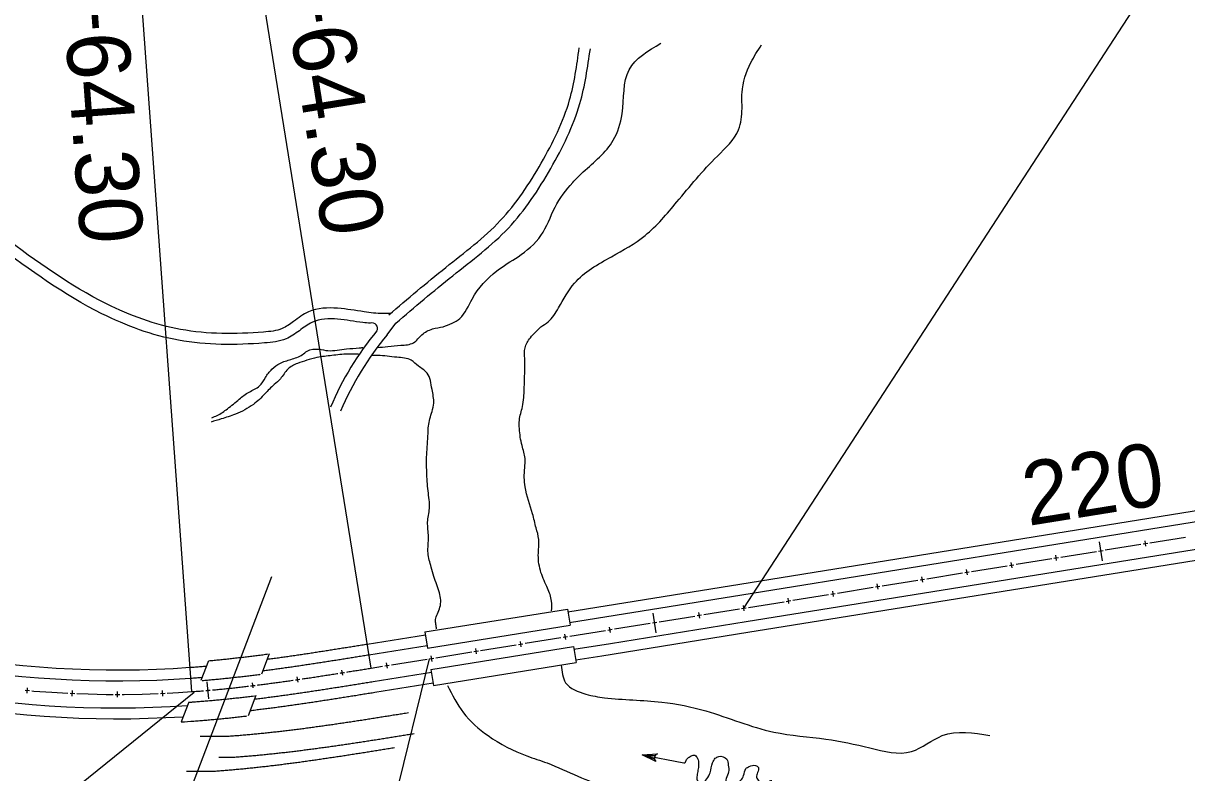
# Model space of a CAD drawing. Extents: x 0 to 34000, y 0 to 22000.
# Drawn here: x 25424 to 27999, y 5602 to 7261 of the extents above; entities that cross this region are included whole.
import ezdxf

# ---------------------------------------------------------------- set-up
doc = ezdxf.new("R2010")
doc.units = 0
for name, color, linetype in [('Default', 7, 'Continuous'), ('GE_P_CL_100', 7, 'Continuous'), ('SH_Text', 7, 'Continuous')]:
    doc.layers.add(name, color=color, linetype=linetype)

msp = doc.modelspace()

# ---------------------------------------------------------------- linework, layer by layer
at = {"layer": 'Default'}
for p, q in [((26229.2, 6571.5), (26248.7, 6596.9)), ((27010.1, 6019.9), (29281, 6385.3)), ((27013.9, 5996.2), (29284.9, 6361.6)), ((27023.5, 5936.9), (29294.4, 6302.4)), ((27027.3, 5913.2), (29298.2, 6278.7)), ((27812.2, 6071.1), (27805.4, 6113.6)), ((27908.3, 6103.6), (27906.4, 6115.5)), ((27710.8, 6071.8), (27708.9, 6083.7)), ((27513.4, 6040.1), (27511.4, 6051.9)), ((27612.1, 6056), (27610.2, 6067.8)), ((25689.3, 5289.1), (25974.1, 6036.7)), ((27414.6, 6024.2), (27412.7, 6036)), ((26629.4, 5958.6), (27010.1, 6019.9)), ((27217.2, 5992.4), (27215.3, 6004.3)), ((27315.9, 6008.3), (27314, 6020.1)), ((26633.2, 5934.9), (27013.9, 5996.2)), ((27118.4, 5976.5), (27116.5, 5988.4)), ((26313, 5913.8), (26628.5, 5964.5)), ((26628.5, 5964.5), (26634.2, 5929)), ((26825, 5912), (26818, 5955.2)), ((26921, 5944.7), (26919.1, 5956.6)), ((27019.7, 5960.6), (27017.8, 5972.5)), ((26318.7, 5878.2), (26634.2, 5929)), ((26723.5, 5913), (26721.6, 5924.8)), ((26723.4, 5888.6), (27023.5, 5936.9)), ((26185.2, 5887.1), (26314, 5907.8)), ((26313, 5913.8), (26318.7, 5878.2)), ((26624.8, 5897.1), (26622.9, 5908.9)), ((26704.2, 5861.2), (27027.3, 5913.2)), ((26189, 5863.4), (26317.8, 5884.1)), ((26326.4, 5830.8), (26641.8, 5881.6)), ((26427.3, 5865.3), (26425.4, 5877.2)), ((26526.1, 5881.2), (26524.2, 5893)), ((26641.8, 5881.6), (26647.5, 5846)), ((26642.8, 5875.7), (26723.4, 5888.6)), ((25834, 5850.3), (25817, 5806.4)), ((25968.4, 5865.2), (25951.2, 5820.7)), ((26229.9, 5833.5), (26228, 5845.4)), ((26328.8, 5848.4), (26326.7, 5861.3)), ((26332.1, 5795.3), (26647.5, 5846)), ((26646.6, 5852), (26704.2, 5861.2)), ((26131.2, 5818), (26129.4, 5829.3)), ((26198.5, 5804.2), (26327.3, 5824.9)), ((26326.4, 5830.8), (26332.1, 5795.3)), ((25834.5, 5765.9), (25831.2, 5803.8)), ((25932.9, 5790.1), (25931.6, 5801.1)), ((26032.3, 5802.6), (26030.5, 5814.9)), ((26202.4, 5780.5), (26331.1, 5801.2)), ((25432.7, 5778.4), (25433.7, 5790.4)), ((25532.8, 5772), (25533.2, 5784)), ((25632.9, 5769.8), (25632.9, 5781.8)), ((25733.2, 5772.1), (25732.6, 5784.1)), ((25938.7, 5773.4), (25922.1, 5728.6)), ((25790.9, 5758.4), (25773.9, 5714.9)), ((25815.6, 5683.4), (25879.9, 5683.4)), ((26794, 5642.2), (26827.3, 5644.4)), ((26794, 5642.2), (26886, 5623.9)), ((26824, 5627.4), (26794, 5642.2)), ((26794, 5642.2), (26820.9, 5633.1)), ((26794, 5642.2), (26822.3, 5640.3)), ((25856.9, 5637.1), (25892.6, 5637.1)), ((25785.1, 5606.1), (25849.4, 5606.1))]:
    msp.add_line(p, q, dxfattribs=at)
for points in [[(27818.5, 6095.2), (27897.4, 6107.9)], [(27902.4, 6108.7), (27912.2, 6110.3)], [(27917.2, 6111.1), (27996.2, 6123.8)], [(27621, 6063.5), (27700, 6076.2)], [(27704.9, 6077), (27714.8, 6078.5)], [(27719.7, 6079.3), (27798.7, 6092.1)], [(27803.6, 6092.8), (27813.5, 6094.4)], [(27522.3, 6047.6), (27601.3, 6060.3)], [(27606.2, 6061.1), (27616.1, 6062.7)], [(27324.8, 6015.8), (27403.8, 6028.5)], [(27408.7, 6029.3), (27418.6, 6030.9)], [(27423.5, 6031.7), (27502.5, 6044.4)], [(27507.5, 6045.2), (27517.3, 6046.8)], [(27211.3, 5997.5), (27221.1, 5999.1)], [(27226.1, 5999.9), (27305.1, 6012.6)], [(27310, 6013.4), (27319.9, 6015)], [(27028.6, 5968.1), (27107.6, 5980.8)], [(27112.5, 5981.6), (27122.4, 5983.2)], [(27127.4, 5984), (27206.3, 5996.7)], [(26831.2, 5936.4), (26910.1, 5949.1)], [(26915.1, 5949.9), (26925, 5951.5)], [(26929.9, 5952.3), (27008.9, 5965)], [(27013.8, 5965.8), (27023.7, 5967.3)], [(26732.4, 5920.5), (26811.4, 5933.2)], [(26816.4, 5934), (26826.2, 5935.6)], [(26535, 5888.7), (26614, 5901.4)], [(26618.9, 5902.2), (26628.8, 5903.8)], [(26633.7, 5904.6), (26712.7, 5917.3)], [(26717.6, 5918.1), (26727.5, 5919.7)], [(26337.5, 5856.9), (26416.5, 5869.6)], [(26421.4, 5870.4), (26431.3, 5872)], [(26436.2, 5872.8), (26515.2, 5885.5)], [(26520.2, 5886.3), (26530, 5887.9)], [(26238.8, 5841), (26317.8, 5853.8)], [(26322.7, 5854.5), (26332.6, 5856.1)], [(26041.3, 5809.9), (26041.8, 5810), (26044.8, 5810.5), (26047.9, 5810.9), (26050.9, 5811.4), (26054, 5811.8), (26057, 5812.3), (26060, 5812.7), (26063.1, 5813.2), (26066.1, 5813.7), (26069.2, 5814.1), (26072.2, 5814.6), (26075.2, 5815), (26078.3, 5815.5), (26081.3, 5816), (26084.4, 5816.4), (26087.4, 5816.9), (26090.5, 5817.4), (26093.5, 5817.9), (26096.5, 5818.3), (26099.6, 5818.8), (26102.6, 5819.3), (26105.7, 5819.8), (26108.7, 5820.2), (26111.7, 5820.7), (26114.8, 5821.2), (26117.8, 5821.7), (26120.4, 5822.1)], [(26125.3, 5822.9), (26126.9, 5823.1), (26130, 5823.6), (26133, 5824.1), (26135.2, 5824.4)], [(26140.2, 5825.2), (26142.1, 5825.5), (26145.2, 5826), (26148.2, 5826.5), (26151.2, 5827), (26154.3, 5827.5), (26157.3, 5827.9), (26160.4, 5828.4), (26163.4, 5828.9), (26166.4, 5829.4), (26169.5, 5829.9), (26172.5, 5830.4), (26175.5, 5830.9), (26178.6, 5831.4), (26181.6, 5831.8), (26184.7, 5832.3), (26187.7, 5832.8), (26190.7, 5833.3), (26193.8, 5833.8)], [(26193.8, 5833.8), (26219, 5837.9)], [(26224, 5838.7), (26233.9, 5840.2)], [(25842.8, 5785.5), (25843.3, 5785.6), (25846.4, 5785.8), (25849.4, 5786.1), (25852.5, 5786.4), (25855.6, 5786.7), (25858.6, 5787), (25861.7, 5787.3), (25864.7, 5787.6), (25867.8, 5787.9), (25870.9, 5788.2), (25873.9, 5788.5), (25877, 5788.9), (25880, 5789.2), (25883.1, 5789.5), (25886.2, 5789.8), (25889.2, 5790.2), (25892.3, 5790.5), (25895.3, 5790.8), (25898.4, 5791.2), (25901.5, 5791.5), (25904.5, 5791.9), (25907.6, 5792.2), (25910.6, 5792.6), (25913.7, 5792.9), (25916.7, 5793.3), (25919.8, 5793.6), (25922.4, 5793.9)], [(25927.4, 5794.5), (25929, 5794.7), (25932, 5795.1), (25935.1, 5795.5), (25937.3, 5795.7)], [(25942.3, 5796.4), (25944.2, 5796.6), (25947.3, 5797), (25950.3, 5797.4), (25953.4, 5797.8), (25956.4, 5798.2), (25959.5, 5798.6), (25962.5, 5798.9), (25965.6, 5799.3), (25968.6, 5799.8), (25971.7, 5800.2), (25974.7, 5800.6), (25977.8, 5801), (25980.8, 5801.4), (25983.9, 5801.8), (25986.9, 5802.2), (25990, 5802.6), (25993, 5803), (25996.1, 5803.5), (25999.1, 5803.9), (26002.2, 5804.3), (26005.2, 5804.7), (26008.3, 5805.2), (26011.3, 5805.6), (26014.4, 5806), (26017.4, 5806.5), (26020.5, 5806.9), (26021.5, 5807.1)], [(26026.5, 5807.8), (26026.6, 5807.8), (26029.6, 5808.2), (26032.6, 5808.7), (26035.7, 5809.1), (26036.4, 5809.2)], [(25428.2, 5784.8), (25438.2, 5784)], [(25443.1, 5783.5), (25447.9, 5783.1), (25487.7, 5780.3), (25523, 5778.4)], [(25528, 5778.2), (25538, 5777.8)], [(25542.9, 5777.6), (25567.6, 5776.8), (25607.6, 5775.8), (25622.9, 5775.8)], [(25627.9, 5775.8), (25637.9, 5775.8)], [(25642.9, 5775.8), (25647.7, 5775.8), (25687.6, 5776.5), (25722.9, 5777.7)], [(25727.9, 5777.9), (25737.9, 5778.4)], [(25742.9, 5778.6), (25767.5, 5779.8), (25797.3, 5781.8)], [(25797.3, 5781.8), (25800.4, 5782), (25803.4, 5782.2), (25806.5, 5782.5), (25809.6, 5782.7), (25812.6, 5782.9), (25815.7, 5783.2), (25818.8, 5783.4), (25821.8, 5783.7), (25822.9, 5783.8)], [(25827.9, 5784.2), (25828, 5784.2), (25831, 5784.5), (25834.1, 5784.7), (25837.2, 5785), (25837.9, 5785.1)]]:
    msp.add_lwpolyline(points, dxfattribs=at)
for centre, radius, start, end in [((25631.8, 8067.6), 2237.8, 214.2163, 274.1413), ((25631.8, 8067.6), 2261.8, 214.2163, 274.1413), ((25631.8, 8067.6), 2345.8, 214.2163, 273.5817), ((25631.8, 8067.6), 2321.8, 214.2163, 273.857), ((26196.4, 6585.7), 11.8, 331.1114, 110.4769), ((26728.2, 6146.9), 677.9, 140.284, 157.0532), ((26750.7, 6138.3), 677.9, 140.284, 157.0532), ((25631.8, 8067.6), 2314.7, 273.9404, 274.1413), ((25631.8, 8067.6), 2357, 273.4557, 274.1413), ((26831, 5634.8), 10.2, 110.9783, 226.5948)]:
    msp.add_arc(centre, radius, start, end, dxfattribs=at)
for points in [[(26353.1, 6589.1), (26390.2, 6607.6), (26417.5, 6650.5), (26472.2, 6713), (26519, 6744.2), (26569.8, 6791.1), (26601, 6853.5), (26640, 6908.2), (26663.4, 6931.6), (26729.8, 7001.8), (26749.3, 7060.4), (26764.9, 7158), (26835.2, 7216.5)], [(26569.8, 6589.1), (26585.4, 6599.8), (26608.8, 6631), (26643.9, 6685.7), (26725.9, 6744.2), (26800.1, 6791.1), (26870.3, 6865.2), (26960.1, 6966.7), (27006.9, 7025.2), (27014.7, 7072.1), (27014.7, 7107.2), (27034.3, 7173.6), (27057.7, 7212.6)], [(26233.4, 6615.4), (26359, 6720.4), (26479.7, 6823.9), (26570.4, 6951.4), (26633.1, 7090.9), (26654.4, 7206.4)], [(26248.7, 6596.9), (26374.5, 6702.1), (26497.6, 6807.5), (26591.4, 6939.4), (26655.8, 7083), (26679, 7204.3)], [(26239.1, 6618.9), (26219.5, 6618.3), (26178.5, 6622.2), (26119.9, 6630), (26055.5, 6622.2), (26022.3, 6600.8), (25997, 6585.2), (25956, 6577.4), (25772.5, 6583.2), (25608.6, 6639.8), (25380.3, 6788.1)], [(26192.3, 6596.8), (26175.7, 6598.4), (26119.8, 6605.9), (26063.9, 6599.1), (26035.2, 6580.5), (26005.8, 6562.4), (25957.9, 6553.3), (25768.1, 6559.3), (25598, 6618.1), (25364.7, 6769.6)], [(26206.8, 6543.2), (26231.2, 6545.2), (26259.5, 6548.1), (26287.8, 6553.9), (26306.3, 6571.5), (26329.7, 6584.2), (26353.1, 6589.1)], [(26593.2, 5960.6), (26593.2, 5982.1), (26584.4, 6010.4), (26569.8, 6045.5), (26563.9, 6083.6), (26564.9, 6118.7), (26559, 6144.1), (26551.2, 6175.3), (26534.6, 6234.8), (26533.7, 6276.8), (26534.6, 6297.3), (26527.8, 6326.6), (26522, 6363.7), (26522, 6382.2), (26528.8, 6412.4), (26532.7, 6452.4), (26533.7, 6484.7), (26533.7, 6518.8), (26534.6, 6542.2), (26546.3, 6564.7), (26569.8, 6589.1)], [(25841.8, 6388), (25853.5, 6392.9), (25876, 6407.6), (25902.3, 6429), (25923.8, 6444.6), (25947.2, 6458.3), (25959.9, 6476.8), (25974.5, 6495.4), (25992.1, 6508.1), (26016.5, 6516.9), (26041.9, 6527.6), (26052.6, 6535.4), (26078, 6539.3), (26098.5, 6536.4), (26139.4, 6540.3), (26167.7, 6542.2), (26175.5, 6543.2)], [(26165.8, 6528.6), (26142.4, 6528.6), (26107.2, 6525.6), (26074.1, 6520.8), (26051.6, 6514.9), (26031.1, 6508.1), (26009.7, 6495.4), (25993.1, 6473.9), (25979.4, 6461.2), (25958.9, 6440.7), (25933.5, 6417.3), (25893.5, 6395.9), (25862.3, 6385.1), (25839.9, 6378.3)], [(26338.5, 5920.6), (26337.5, 5930.4), (26336.5, 5941.1), (26340.5, 5953.8), (26346.3, 5968.4), (26345.3, 6000.7), (26339.5, 6018.2), (26332.6, 6036.8), (26326.8, 6057.2), (26320, 6088.5), (26320.9, 6124.6), (26319, 6156.8), (26322.9, 6187), (26320, 6226.1), (26317, 6268), (26317, 6306.1), (26320, 6352.9), (26320.9, 6369.5), (26328.7, 6401.7), (26332.6, 6420.2), (26328.7, 6450.5), (26318, 6486.6), (26298.5, 6502.2), (26282.9, 6514.9), (26250.7, 6521.7), (26208.7, 6525.6), (26195.1, 6525.6)], [(25963.9, 5853.6), (25967.6, 5854.1), (25973.6, 5854.9), (25979.6, 5855.7), (25985.7, 5856.5), (25991.7, 5857.4), (25997.7, 5858.2), (26003.7, 5859.1), (26009.8, 5859.9), (26015.8, 5860.8), (26021.8, 5861.7), (26027.9, 5862.5), (26033.9, 5863.4), (26039.9, 5864.3), (26046, 5865.2), (26052, 5866.1), (26058, 5867), (26064.1, 5868), (26070.1, 5868.9), (26076.1, 5869.8), (26082.2, 5870.8), (26088.2, 5871.7), (26094.3, 5872.6), (26100.3, 5873.6), (26106.4, 5874.5), (26112.4, 5875.5), (26118.5, 5876.4), (26124.5, 5877.4), (26130.6, 5878.4), (26136.7, 5879.3), (26142.7, 5880.3), (26148.8, 5881.3), (26154.8, 5882.2), (26160.9, 5883.2), (26167, 5884.2), (26173.1, 5885.2), (26179.1, 5886.1), (26185.2, 5887.1)], [(25836.6, 5850.4), (25840.4, 5850.7), (25846.3, 5851.3), (25852.3, 5851.9), (25858.3, 5852.5), (25864.3, 5853.1), (25870.2, 5853.7), (25876.2, 5854.3), (25882.2, 5854.9), (25888.2, 5855.6), (25894.2, 5856.3), (25900.2, 5857), (25906.2, 5857.6), (25912.1, 5858.3), (25918.1, 5859.1), (25924.1, 5859.8), (25930.1, 5860.5), (25936.1, 5861.3), (25942.1, 5862), (25948.1, 5862.8), (25954.1, 5863.6), (25960.1, 5864.4), (25965.6, 5865.1)], [(25954.1, 5828.1), (25958.7, 5828.7), (25964.7, 5829.5), (25970.8, 5830.3), (25976.8, 5831.1), (25982.9, 5831.9), (25988.9, 5832.8), (25995, 5833.6), (26001.1, 5834.5), (26007.1, 5835.3), (26013.2, 5836.2), (26019.2, 5837), (26025.3, 5837.9), (26031.3, 5838.8), (26037.4, 5839.7), (26043.5, 5840.6), (26049.5, 5841.5), (26055.6, 5842.4), (26061.6, 5843.3), (26067.7, 5844.2), (26073.7, 5845.2), (26079.8, 5846.1), (26085.9, 5847), (26091.9, 5848), (26098, 5848.9), (26104, 5849.9), (26110.1, 5850.8), (26116.2, 5851.8), (26122.2, 5852.7), (26128.3, 5853.7), (26134.4, 5854.7), (26140.4, 5855.6), (26146.5, 5856.6), (26152.6, 5857.6), (26158.6, 5858.5), (26164.7, 5859.5), (26170.8, 5860.5), (26176.9, 5861.5), (26182.9, 5862.4), (26189, 5863.4)], [(25793.4, 5835.6), (25799.4, 5836.1), (25805.4, 5836.5), (25811.4, 5837), (25817.4, 5837.5), (25823.4, 5838), (25829.4, 5838.5), (25829.5, 5838.5)], [(25819.9, 5806.4), (25820, 5806.4), (25826, 5807), (25832.1, 5807.5), (25838.2, 5808), (25844.3, 5808.6), (25850.3, 5809.2), (25856.4, 5809.7), (25862.5, 5810.3), (25868.5, 5810.9), (25874.6, 5811.6), (25880.7, 5812.2), (25886.8, 5812.9), (25892.8, 5813.5), (25898.9, 5814.2), (25905, 5814.9), (25911, 5815.6), (25917.1, 5816.3), (25923.2, 5817), (25929.3, 5817.8), (25935.3, 5818.5), (25941.4, 5819.3), (25947.5, 5820), (25948.4, 5820.1)], [(26614.7, 5840.6), (26624.4, 5801.6), (26669.3, 5776.2), (26710.3, 5768.4), (26837.1, 5758.7), (26934.7, 5739.1), (27085, 5692.3), (27200.1, 5676.7), (27297.7, 5657.2), (27389.4, 5649.4), (27457.8, 5684.5), (27563.1, 5684.5)], [(25795.1, 5811.7), (25801.2, 5812.2), (25807.3, 5812.6), (25813.3, 5813.1), (25819.4, 5813.6), (25819.8, 5813.6)], [(25935.7, 5765.3), (25941.8, 5766.1), (25948, 5766.8), (25954.1, 5767.6), (25960.3, 5768.4), (25966.4, 5769.2), (25972.6, 5770), (25978.7, 5770.8), (25984.9, 5771.6), (25991, 5772.5), (25997.1, 5773.3), (26003.3, 5774.2), (26009.4, 5775), (26015.5, 5775.9), (26021.7, 5776.8), (26027.8, 5777.7), (26033.9, 5778.5), (26040, 5779.4), (26046.2, 5780.3), (26052.3, 5781.2), (26058.4, 5782.2), (26064.5, 5783.1), (26070.6, 5784), (26076.7, 5784.9), (26082.8, 5785.9), (26088.9, 5786.8), (26095, 5787.7), (26101.1, 5788.7), (26107.2, 5789.6), (26113.3, 5790.6), (26119.4, 5791.5), (26125.5, 5792.5), (26131.6, 5793.5), (26137.7, 5794.4), (26143.8, 5795.4), (26149.9, 5796.4), (26156, 5797.3), (26162.1, 5798.3), (26168.1, 5799.3), (26174.2, 5800.3), (26180.3, 5801.2), (26186.4, 5802.2), (26192.5, 5803.2), (26198.5, 5804.2)], [(26362.9, 5795.7), (26398, 5735.2), (26452.7, 5684.5), (26538.5, 5639.6), (26583.4, 5624), (26651.7, 5594.7), (26774.7, 5542), (26839.1, 5510.8), (26948.4, 5491.3), (27014.7, 5491.3), (27085, 5477.6), (27188.4, 5444.4), (27209.9, 5401.5), (27258.7, 5376.1), (27307.5, 5385.9), (27352.4, 5397.6), (27420.7, 5378.1), (27469.5, 5346.9), (27526.1, 5315.6), (27639.3, 5270.7), (27729, 5249.3)], [(25799, 5759), (25805.1, 5759.5), (25811.3, 5759.9), (25817.5, 5760.4), (25823.7, 5760.9), (25829.9, 5761.5), (25836.1, 5762), (25842.3, 5762.5), (25848.5, 5763.1), (25854.7, 5763.7), (25860.8, 5764.3), (25867, 5764.9), (25873.2, 5765.5), (25879.3, 5766.1), (25885.5, 5766.8), (25891.7, 5767.5), (25897.8, 5768.1), (25904, 5768.8), (25910.2, 5769.5), (25916.3, 5770.2), (25922.5, 5771), (25928.6, 5771.7), (25934.8, 5772.4), (25936, 5772.6)], [(25926.4, 5740), (25932.4, 5740.7), (25938.6, 5741.5), (25944.8, 5742.3), (25951, 5743), (25957.2, 5743.8), (25963.3, 5744.6), (25969.5, 5745.4), (25975.7, 5746.2), (25981.9, 5747), (25988.1, 5747.9), (25994.2, 5748.7), (26000.4, 5749.6), (26006.6, 5750.4), (26012.7, 5751.3), (26018.9, 5752.1), (26025.1, 5753), (26031.2, 5753.9), (26037.4, 5754.8), (26043.5, 5755.7), (26049.7, 5756.6), (26055.8, 5757.5), (26061.9, 5758.4), (26068.1, 5759.3), (26074.2, 5760.3), (26080.3, 5761.2), (26086.5, 5762.1), (26092.6, 5763.1), (26098.7, 5764), (26104.8, 5765), (26110.9, 5765.9), (26117.1, 5766.9), (26123.2, 5767.8), (26129.3, 5768.8), (26135.4, 5769.8), (26141.5, 5770.7), (26147.6, 5771.7), (26153.7, 5772.7), (26159.8, 5773.6), (26165.9, 5774.6), (26171.9, 5775.6), (26178, 5776.6), (26184.1, 5777.6), (26190.2, 5778.5), (26196.3, 5779.5), (26202.4, 5780.5)], [(25802, 5716.8), (25808.3, 5717.3), (25814.6, 5717.7), (25820.9, 5718.2), (25827.2, 5718.7), (25833.5, 5719.3), (25839.8, 5719.8), (25846.1, 5720.4), (25852.4, 5721), (25858.7, 5721.5), (25864.9, 5722.1), (25871.2, 5722.8), (25877.5, 5723.4), (25883.7, 5724), (25890, 5724.7), (25896.2, 5725.4), (25902.5, 5726.1), (25908.7, 5726.8), (25915, 5727.5), (25919, 5727.9)], [(25879.9, 5683.4), (25886, 5683.9), (25892.2, 5684.4), (25898.3, 5684.8), (25904.4, 5685.3), (25910.6, 5685.9), (25916.7, 5686.4), (25922.8, 5686.9), (25929, 5687.5), (25935.1, 5688.1), (25941.2, 5688.7), (25947.3, 5689.3), (25953.5, 5689.9), (25959.6, 5690.5), (25965.7, 5691.2), (25971.8, 5691.8), (25977.9, 5692.5), (25984.1, 5693.2), (25990.2, 5693.9), (25996.3, 5694.6), (26002.4, 5695.3), (26008.5, 5696), (26014.6, 5696.7), (26020.7, 5697.5), (26026.8, 5698.3), (26032.9, 5699), (26039, 5699.8), (26045.2, 5700.6), (26051.3, 5701.4), (26057.4, 5702.2), (26063.5, 5703), (26069.6, 5703.9), (26075.6, 5704.7), (26081.7, 5705.5), (26087.8, 5706.4), (26093.9, 5707.3), (26100, 5708.1), (26106.1, 5709), (26112.2, 5709.9), (26118.3, 5710.8), (26124.4, 5711.7), (26130.5, 5712.6), (26136.6, 5713.5), (26142.6, 5714.4), (26148.7, 5715.3), (26154.8, 5716.2), (26160.9, 5717.2), (26167, 5718.1), (26173.1, 5719), (26179.1, 5720), (26185.2, 5720.9), (26191.3, 5721.9), (26197.4, 5722.8), (26203.5, 5723.8), (26209.5, 5724.8), (26215.6, 5725.7), (26221.7, 5726.7), (26227.8, 5727.7), (26233.8, 5728.6), (26239.9, 5729.6), (26246, 5730.6), (26252.1, 5731.5), (26258.2, 5732.5), (26264.2, 5733.5), (26270.3, 5734.5), (26276.4, 5735.5)], [(25892.6, 5637.1), (25898.7, 5637.5), (25904.9, 5638), (25911, 5638.5), (25917.1, 5639), (25923.3, 5639.5), (25929.4, 5640), (25935.5, 5640.6), (25941.7, 5641.1), (25947.8, 5641.7), (25953.9, 5642.3), (25960, 5642.9), (25966.2, 5643.5), (25972.3, 5644.2), (25978.4, 5644.8), (25984.5, 5645.5), (25990.6, 5646.1), (25996.7, 5646.8), (26002.9, 5647.5), (26009, 5648.2), (26015.1, 5648.9), (26021.2, 5649.7), (26027.3, 5650.4), (26033.4, 5651.1), (26039.5, 5651.9), (26045.6, 5652.7), (26051.7, 5653.5), (26057.8, 5654.2), (26063.9, 5655), (26070, 5655.9), (26076.1, 5656.7), (26082.2, 5657.5), (26088.3, 5658.3), (26094.4, 5659.2), (26100.5, 5660), (26106.6, 5660.9), (26112.7, 5661.8), (26118.8, 5662.6), (26124.9, 5663.5), (26131, 5664.4), (26137.1, 5665.3), (26143.2, 5666.2), (26149.2, 5667.1), (26155.3, 5668), (26161.4, 5669), (26167.5, 5669.9), (26173.6, 5670.8), (26179.7, 5671.7), (26185.7, 5672.7), (26191.8, 5673.6), (26197.9, 5674.6), (26204, 5675.5), (26210.1, 5676.5), (26216.1, 5677.4), (26222.2, 5678.4), (26228.3, 5679.4), (26234.4, 5680.3), (26240.5, 5681.3), (26246.5, 5682.3), (26252.6, 5683.2), (26258.7, 5684.2), (26264.8, 5685.2), (26270.8, 5686.2), (26276.9, 5687.1), (26283, 5688.1), (26289.1, 5689.1)], [(25849.4, 5606.1), (25855.5, 5606.6), (25861.6, 5607), (25867.8, 5607.5), (25873.9, 5608), (25880.1, 5608.5), (25886.2, 5609.1), (25892.3, 5609.6), (25898.4, 5610.2), (25904.6, 5610.8), (25910.7, 5611.3), (25916.8, 5611.9), (25922.9, 5612.6), (25929.1, 5613.2), (25935.2, 5613.8), (25941.3, 5614.5), (25947.4, 5615.2), (25953.5, 5615.8), (25959.6, 5616.5), (25965.8, 5617.2), (25971.9, 5618), (25978, 5618.7), (25984.1, 5619.4), (25990.2, 5620.2), (25996.3, 5620.9), (26002.4, 5621.7), (26008.5, 5622.5), (26014.6, 5623.3), (26020.7, 5624.1), (26026.8, 5624.9), (26032.9, 5625.7), (26039, 5626.5), (26045.1, 5627.4), (26051.2, 5628.2), (26057.3, 5629.1), (26063.4, 5629.9), (26069.5, 5630.8), (26075.6, 5631.7), (26081.7, 5632.6), (26087.8, 5633.5), (26093.9, 5634.3), (26099.9, 5635.2), (26106, 5636.2), (26112.1, 5637.1), (26118.2, 5638), (26124.3, 5638.9), (26130.4, 5639.8), (26136.4, 5640.8), (26142.5, 5641.7), (26148.6, 5642.7), (26154.7, 5643.6), (26160.8, 5644.6), (26166.9, 5645.5), (26172.9, 5646.5), (26179, 5647.4), (26185.1, 5648.4), (26191.2, 5649.4), (26197.2, 5650.3), (26203.3, 5651.3), (26209.4, 5652.3), (26215.5, 5653.3), (26221.5, 5654.2), (26227.6, 5655.2), (26233.7, 5656.2), (26239.8, 5657.2), (26245.9, 5658.1)], [(26886, 5623.9), (26888.3, 5624.2), (26890.3, 5627.8), (26894.4, 5634.3), (26901.9, 5639.4), (26910.5, 5640.9), (26914.1, 5637.4), (26917.6, 5630.8), (26918.6, 5620.2), (26917.1, 5608), (26915.1, 5596.4), (26915.6, 5585.8), (26926.2, 5581.3), (26936.8, 5588.8), (26943.9, 5602.5), (26949.5, 5624.2), (26955.5, 5634.3), (26963.1, 5638.4), (26980.8, 5632.3), (26984.3, 5619.2), (26984.8, 5604), (26979.8, 5589.8), (26979.8, 5579.2), (26989.9, 5574.7), (27000.5, 5575.2), (27012.1, 5585.8), (27018.2, 5595.9), (27023.2, 5611.6), (27030.8, 5616.1), (27044.5, 5618.7), (27051, 5613.6), (27049, 5603), (27047, 5592.4), (27051.5, 5583.8), (27055.6, 5579.2), (27064.2, 5577.7), (27071.8, 5579.7), (27076.3, 5584.3), (27080.3, 5585.4)]]:
    msp.add_spline(points, degree=3, dxfattribs=at)
at = {"layer": 'GE_P_CL_100'}
for p, q in [((25797.3, 5781.8), (25596, 8562.1)), ((26193.8, 5833.8), (25754.3, 8564.7)), ((26322.5, 5854.6), (26124.4, 5049.7)), ((25802.5, 5779.9), (25351.3, 5416.6))]:
    msp.add_line(p, q, dxfattribs=at)
at = {"layer": 'SH_Text'}
msp.add_line((27018.8, 5966.6), (29038.3, 9071.1), dxfattribs=at)

# ---------------------------------------------------------------- texts
at = {"layer": 'GE_P_CL_100'}
for s, rotation, p in [('C.S. STA. 199+64.30', 274.1414, (25423.5, 8538.3)), ('S.T. STA. 203+64.30', 279.1416, (25810, 8514)), ('220', 9.1389, (27647.7, 6148.3))]:
    msp.add_text(s, height=140, rotation=rotation, dxfattribs=at).set_placement(p)

doc.saveas('drawing.dxf')
